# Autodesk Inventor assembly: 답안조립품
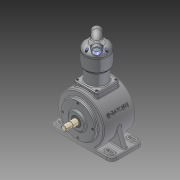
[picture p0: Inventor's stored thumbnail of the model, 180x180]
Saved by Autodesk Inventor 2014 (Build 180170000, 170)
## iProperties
Created: 2015-06
Part Number: 답안조립품
Document SubType Name: Assembly
Designer: 학생용
Author: 학생용
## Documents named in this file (15)
- C:\Users\학생용\Desktop\답안조립품.iam
- C:\Users\학생용\Desktop\본체.ipt
- C:\Users\학생용\Desktop\450605V1008\베어링 6204.ipt
- C:\Users\학생용\Desktop\450605V1008\메인커버.ipt
- C:\Users\학생용\Desktop\450605V1008\오일실.ipt
- C:\Users\학생용\Desktop\450605V1008\크랭크 서브축.ipt
- C:\Users\학생용\Desktop\450605V1008\메인 크랭크 축-구동부.ipt
- C:\Users\학생용\Desktop\450605V1008\실린더.ipt
- C:\Users\학생용\Desktop\450605V1008\피스톤.ipt
- C:\Users\학생용\Desktop\450605V1008\피스톤 핀.ipt
- C:\Users\학생용\Desktop\450605V1008\베어링 NA 4902.ipt
- C:\Users\학생용\Desktop\450605V1008\커넥팅 로드.ipt
- C:\Users\학생용\Desktop\450605V1008\실린더헤드.ipt
- C:\Users\학생용\Desktop\450605V1008\M5x0.8.ipt
- C:\Users\학생용\Desktop\450605V1008\M4x0.7.ipt
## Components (14 placed, 4 different names)
1. 피스톤:1
2. 피스톤 핀:1
3. M5x0.8:1
4. M5x0.8:2
5. M5x0.8:3
6. M5x0.8:4
7. M4x0.7:1
8. M4x0.7:2
9. M4x0.7:3
10. M4x0.7:4
11. M4x0.7:5
12. M4x0.7:6
13. M4x0.7:7
14. M4x0.7:8
